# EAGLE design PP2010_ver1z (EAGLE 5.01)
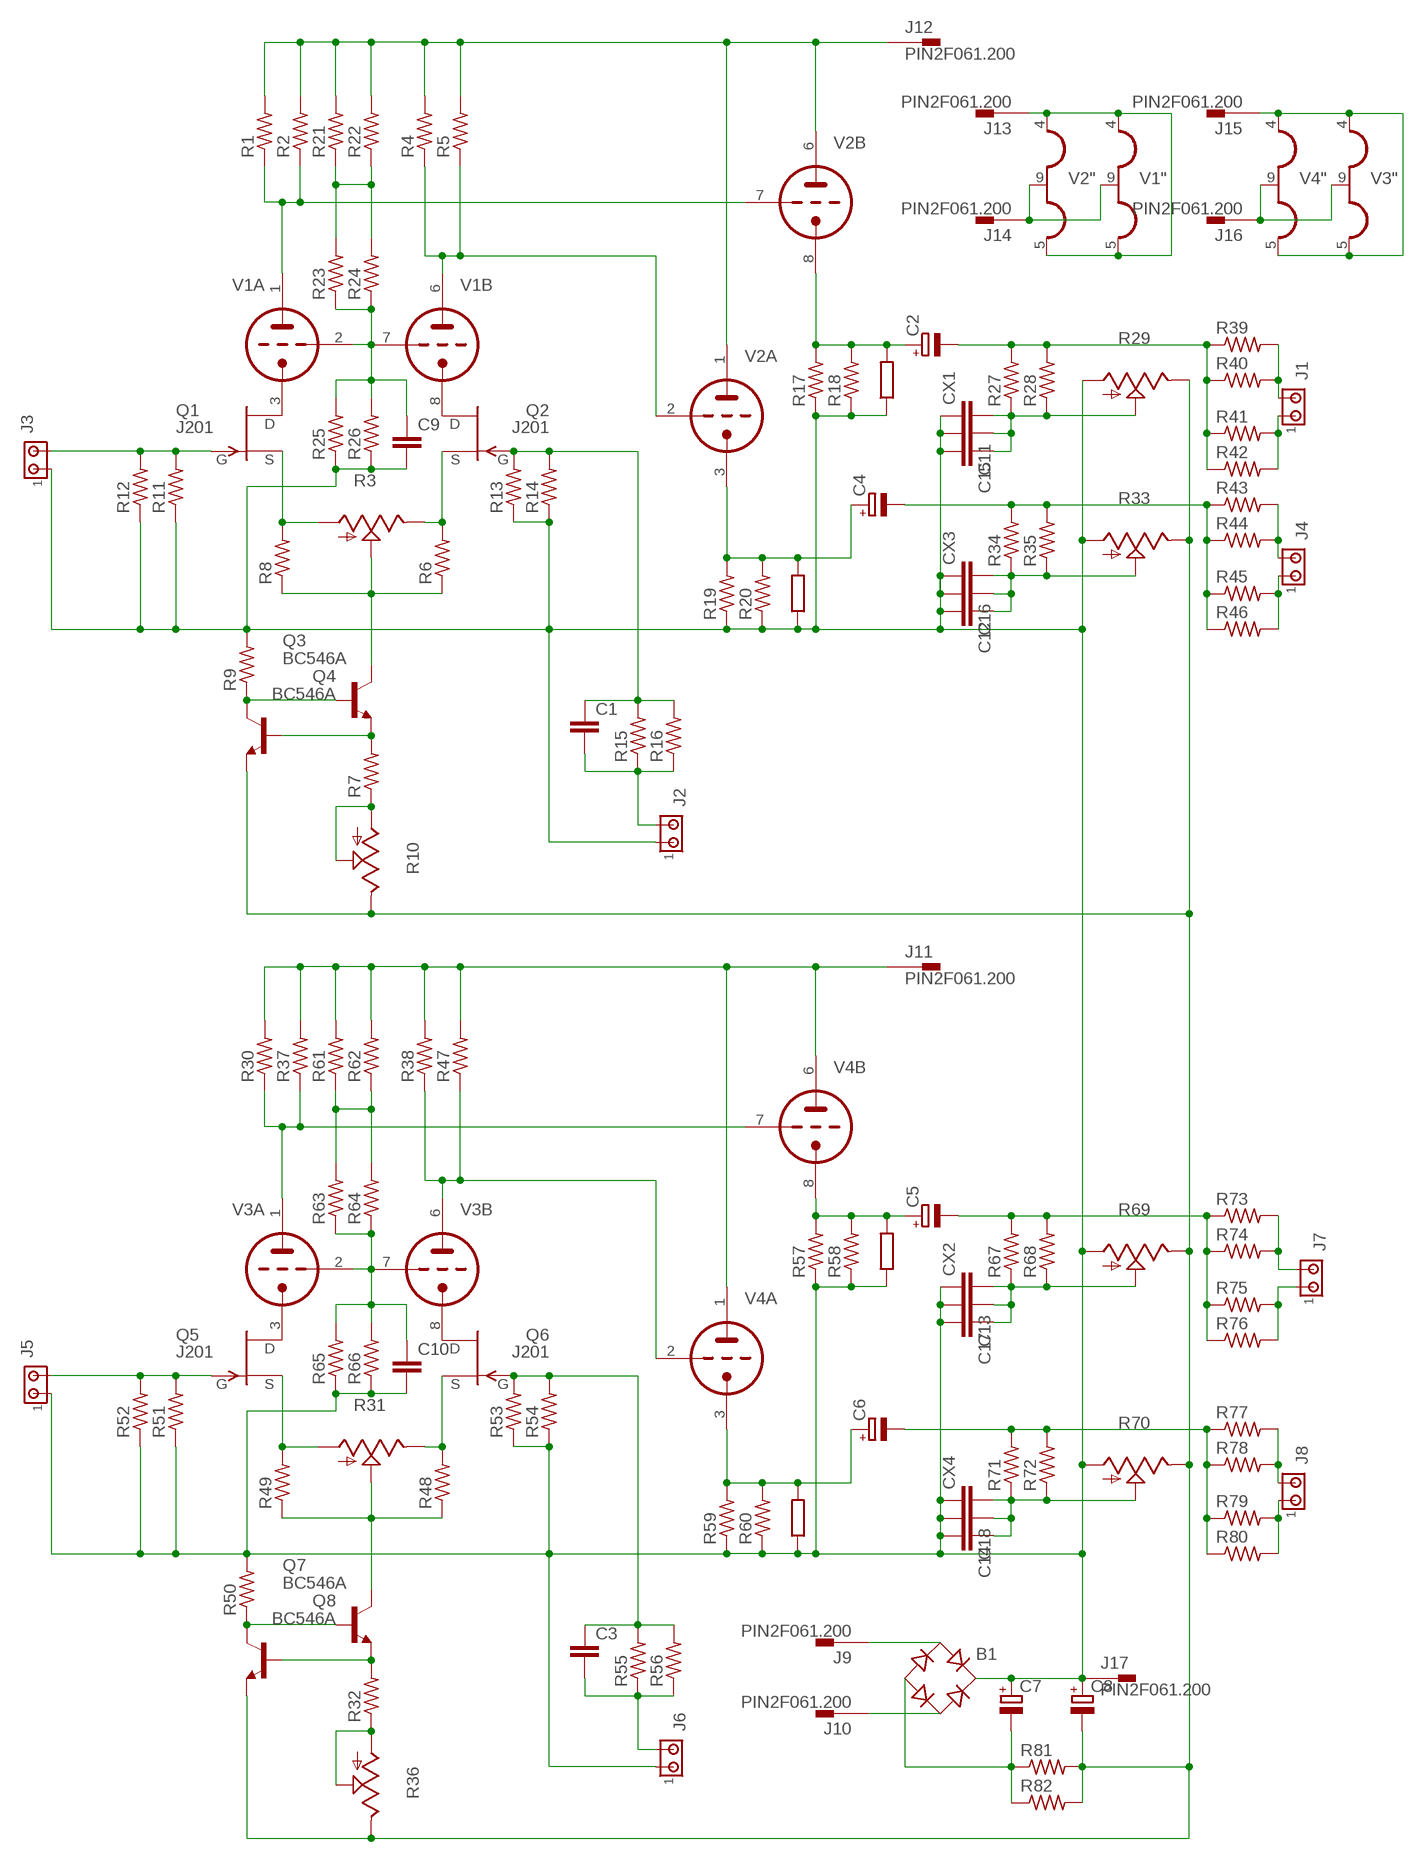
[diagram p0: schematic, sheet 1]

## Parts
B1  RB1A  [RB1A]
C1  C-EU025-050X050  [C025-050X050]
C2  CPOL-EUE55-30AXIAL  [E55-30]
C3  C-EU025-050X050  [C025-050X050]
C4  CPOL-EUE55-30AXIAL  [E55-30]
C5  CPOL-EUE55-30AXIAL  [E55-30]
C6  CPOL-EUE55-30AXIAL  [E55-30]
C7  CPOL-EUE7.5-18  [E7,5-18]
C8  CPOL-EUE7.5-18  [E7,5-18]
C9  C-EU150-091X182  [C150-091X182]
C10  C-EU150-091X182  [C150-091X182]
C11  C-EU275-134X316  [C275-134X316]
C12  C-EU275-134X316  [C275-134X316]
C13  C-EU275-134X316  [C275-134X316]
C14  C-EU275-134X316  [C275-134X316]
C15  C-EU150-084X183  [C150-084X183]
C16  C-EU150-084X183  [C150-084X183]
C17  C-EU150-084X183  [C150-084X183]
C18  C-EU150-084X183  [C150-084X183]
CX1  CXXC22B7  [XC22B7]
CX2  CXXC22B7  [XC22B7]
CX3  CXXC22B7  [XC22B7]
CX4  CXXC22B7  [XC22B7]
J1  MTA02-100  [10X02MTA]
J2  MTA02-100  [10X02MTA]
J3  MTA02-100  [10X02MTA]
J4  MTA02-100  [10X02MTA]
J5  MTA02-100  [10X02MTA]
J6  MTA02-100  [10X02MTA]
J7  MTA02-100  [10X02MTA]
J8  MTA02-100  [10X02MTA]
J9  PIN2F061.200  [F061.200]
J10  PIN2F061.200  [F061.200]
J11  PIN2F061.200  [F061.200]
J12  PIN2F061.200  [F061.200]
J13  PIN2F061.200  [F061.200]
J14  PIN2F061.200  [F061.200]
J15  PIN2F061.200  [F061.200]
J16  PIN2F061.200  [F061.200]
J17  PIN2F061.200  [F061.200]
Q1  J201  [TO92]
Q2  J201  [TO92]
Q3  BC546A  [TO92-EBC]
Q4  BC546A  [TO92-EBC]
Q5  J201  [TO92]
Q6  J201  [TO92]
Q7  BC546A  [TO92-EBC]
Q8  BC546A  [TO92-EBC]
R1  R-US_0207/7  [0207/7]
R2  R-US_0207/7  [0207/7]
R3  TRIM_US-B64Y  [B64Y]
R4  R-US_0207/7  [0207/7]
R5  R-US_0207/7  [0207/7]
R6  R-US_0207/7  [0207/7]
R7  R-US_0207/7  [0207/7]
R8  R-US_0207/7  [0207/7]
R9  R-US_0207/7  [0207/7]
R10  TRIM_US-B64Y  [B64Y]
R11  R-US_0207/7  [0207/7]
R12  R-US_0207/7  [0207/7]
R13  R-US_0207/7  [0207/7]
R14  R-US_0207/7  [0207/7]
R15  R-US_0207/7  [0207/7]
R16  R-US_0207/7  [0207/7]
R17  R-US_0617/22  [0617/22]
R18  R-US_0617/22  [0617/22]
R19  R-US_0617/22  [0617/22]
R20  R-US_0617/22  [0617/22]
R21  R-US_0207/7  [0207/7]
R22  R-US_0207/7  [0207/7]
R23  R-US_0207/7  [0207/7]
R24  R-US_0207/7  [0207/7]
R25  R-US_0207/7  [0207/7]
R26  R-US_0207/7  [0207/7]
R27  R-US_0309/10  [0309/10]
R28  R-US_0309/10  [0309/10]
R29  TRIM_US-B64Y  [B64Y]
R30  R-US_0207/7  [0207/7]
R31  TRIM_US-B64Y  [B64Y]
R32  R-US_0207/7  [0207/7]
R33  TRIM_US-B64Y  [B64Y]
R34  R-US_0309/10  [0309/10]
R35  R-US_0309/10  [0309/10]
R36  TRIM_US-B64Y  [B64Y]
R37  R-US_0207/7  [0207/7]
R38  R-US_0207/7  [0207/7]
R39  R-US_0309/10  [0309/10]
R40  R-US_0309/10  [0309/10]
R41  R-US_0309/10  [0309/10]
R42  R-US_0309/10  [0309/10]
R43  R-US_0309/10  [0309/10]
R44  R-US_0309/10  [0309/10]
R45  R-US_0309/10  [0309/10]
R46  R-US_0309/10  [0309/10]
R47  R-US_0207/7  [0207/7]
R48  R-US_0207/7  [0207/7]
R49  R-US_0207/7  [0207/7]
R50  R-US_0207/7  [0207/7]
R51  R-US_0207/7  [0207/7]
R52  R-US_0207/7  [0207/7]
R53  R-US_0207/7  [0207/7]
R54  R-US_0207/7  [0207/7]
R55  R-US_0207/7  [0207/7]
R56  R-US_0207/7  [0207/7]
R57  R-US_0617/22  [0617/22]
R58  R-US_0617/22  [0617/22]
R59  R-US_0617/22  [0617/22]
R60  R-US_0617/22  [0617/22]
R61  R-US_0207/7  [0207/7]
R62  R-US_0207/7  [0207/7]
R63  R-US_0207/7  [0207/7]
R64  R-US_0207/7  [0207/7]
R65  R-US_0207/7  [0207/7]
R66  R-US_0207/7  [0207/7]
R67  R-US_0309/10  [0309/10]
R68  R-US_0309/10  [0309/10]
R69  TRIM_US-B64Y  [B64Y]
R70  TRIM_US-B64Y  [B64Y]
R71  R-US_0309/10  [0309/10]
R72  R-US_0309/10  [0309/10]
R73  R-US_0309/10  [0309/10]
R74  R-US_0309/10  [0309/10]
R75  R-US_0309/10  [0309/10]
R76  R-US_0309/10  [0309/10]
R77  R-US_0309/10  [0309/10]
R78  R-US_0309/10  [0309/10]
R79  R-US_0309/10  [0309/10]
R80  R-US_0309/10  [0309/10]
R81  R-US_0617/22  [0617/22]
R82  R-US_0617/22  [0617/22]
U$1  MP820  [MP820]
U$2  MP820  [MP820]
U$3  MP820  [MP820]
U$4  MP820  [MP820]
V1  12AX7-P  [NOVAL]
V2  12AU7-P  [NOVAL]
V3  12AX7-P  [NOVAL]
V4  12AU7-P  [NOVAL]

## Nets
N$1: C4.- R34.2 R35.2 R43.1 R44.1 R45.1 R46.1
N$2: R1.1 R2.1 V1.1(A:TA) V2.7(B:TG)
N$3: Q3.E Q4.B R7.2
N$4: R4.1 R5.1 V1.6(B:TA) V2.2(A:TG)
N$5: J12.1A R1.2 R2.2 R4.2 R5.2 R21.2 R22.2 V2.1(A:TA) V2.6(B:TA)
N$6: Q1.3(D) V1.3(A:TK)
N$7: Q2.3(D) V1.8(B:TK)
N$8: Q1.2(S) R3.A R8.2
N$9: C2.+ R17.2 R18.2 U$4.OUT V2.8(B:TK)
N$10: Q2.2(S) R3.E R6.2
N$11: R7.1 R10.A R10.S
N$12: Q3.C R3.S R6.1 R8.1
N$13: Q3.B Q4.C R9.1
N$14: C8.- Q4.E Q8.E R10.E R29.E R33.E R36.E R69.E R70.E R81.2 R82.2
N$15: J3.2 Q1.1(G) R11.2 R12.2
N$16: R21.1 R22.1 R23.2 R24.2
N$17: B1.AC1 J9.1A
N$18: C4.+ R19.2 R20.2 U$3.OUT V2.3(A:TK)
N$19: C1.1 Q2.1(G) R13.2 R14.2 R15.2 R16.2
N$20: C1.2 J2.2 R15.1 R16.1
N$21: C9.1 R23.1 R24.1 R25.2 R26.2 V1.2(A:TG) V1.7(B:TG)
N$22: C2.- R27.2 R28.2 R39.1 R40.1 R41.1 R42.1
N$23: C11.1 C15.1 CX1.2 R27.1 R28.1 R29.S
N$24: J1.2 R39.2 R40.2
N$25: J1.1 R41.2 R42.2
N$26: J4.2 R43.2 R44.2
N$27: J4.1 R45.2 R46.2
N$28: B1.AC2 J10.1A
N$29: Q6.2(S) R31.E R48.2
N$30: C12.1 C16.1 CX3.2 R33.S R34.1 R35.1
N$31: R30.1 R37.1 V3.1(A:TA) V4.7(B:TG)
N$32: R38.1 R47.1 V3.6(B:TA) V4.2(A:TG)
N$33: J11.1A R30.2 R37.2 R38.2 R47.2 R61.2 R62.2 V4.1(A:TA) V4.6(B:TA)
N$34: Q5.3(D) V3.3(A:TK)
N$35: Q6.3(D) V3.8(B:TK)
N$36: Q5.2(S) R31.A R49.2
N$37: Q7.C R31.S R48.1 R49.1
N$38: Q7.E Q8.B R32.2
N$39: R32.1 R36.A R36.S
N$40: Q7.B Q8.C R50.1
N$41: J15.1A V3.4(":H1) V3.5(":H3) V4.4(":H1) V4.5(":H3)
N$42: J5.2 Q5.1(G) R51.2 R52.2
N$43: C3.1 Q6.1(G) R53.2 R54.2 R55.2 R56.2
N$44: C3.2 J6.2 R55.1 R56.1
N$45: C5.+ R57.2 R58.2 U$2.OUT V4.8(B:TK)
N$46: J16.1A V3.9(":H2) V4.9(":H2)
N$47: C6.+ R59.2 R60.2 U$1.OUT V4.3(A:TK)
N$48: C5.- R67.2 R68.2 R73.1 R74.1 R75.1 R76.1
N$49: C6.- R71.2 R72.2 R77.1 R78.1 R79.1 R80.1
N$50: R61.1 R62.1 R63.2 R64.2
N$51: C10.1 R63.1 R64.1 R65.2 R66.2 V3.2(A:TG) V3.7(B:TG)
N$52: C13.1 C17.1 CX2.2 R67.1 R68.1 R69.S
N$53: C14.1 C18.1 CX4.2 R70.S R71.1 R72.1
N$54: J7.2 R73.2 R74.2
N$55: J7.1 R75.2 R76.2
N$56: J8.2 R77.2 R78.2
N$57: J8.1 R79.2 R80.2
N$58: B1.- C7.- R81.1 R82.1
N$59: B1.+ C7.+ C8.+ C9.2 C10.2 C11.2 C12.2 C13.2 C14.2 C15.2 C16.2 C17.2 C18.2 CX1.1 CX2.1 CX3.1 CX4.1 J2.1 J3.1 J5.1 J6.1 J17.1A R9.2 R11.1 R12.1 R13.1 R14.1 R17.1 R18.1 R19.1 R20.1 R25.1 R26.1 R29.A R33.A R50.2 R51.1 R52.1 R53.1 R54.1 R57.1 R58.1 R59.1 R60.1 R65.1 R66.1 R69.A R70.A U$1.IN U$2.IN U$3.IN U$4.IN
N$60: J13.1A V1.4(":H1) V1.5(":H3) V2.4(":H1) V2.5(":H3)
N$61: J14.1A V1.9(":H2) V2.9(":H2)
Unconnected: J9.1B(1.1) J10.1B(1.1) J11.1B(1.1) J12.1B(1.1) J13.1B(1.1) J14.1B(1.1) J15.1B(1.1) J16.1B(1.1) J17.1B(1.1)

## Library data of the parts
B1 = rectifier:RB1A: RECTIFIER 1 A
C1 C3 C9-C18 = rcl:C-EU: CAPACITOR, European symbol
C2 C4-C6 = resistor:CPOL-EU: POLARIZED CAPACITOR, European symbol
C7 C8 = rcl:CPOL-EU: POLARIZED CAPACITOR, European symbol
CX1-CX4 = resistor:CX: X CAPACITOR
J1-J8 = con-amp:MTA02-100: AMP connector
J9-J17 = con-faston:PIN2: Flachstecker Typ Tyco/Electronics/AMP TAB, FASTON
Q1 Q2 Q5 Q6 = transistor-fet:?20*: TEMIC / Siliconix N-Channel JFET Source: JFET-J201_Siliconix_data.pdf
Q3 Q4 Q7 Q8 = transistor-npn:BC546*: NPN Transistor
R1 R2 R4-R9 R11-R16 R21-R26 R30 R32 R37 R38 R47-R56 R61-R66 R81 R82 = rcl:R-US_: RESISTOR, American symbol
R3 R10 R29 R31 R33 R36 R69 R70 = pot:TRIM_US-: POTENTIOMETER
R17-R20 R27 R28 R34 R35 R39-R46 R57-R60 R67 R68 R71-R80 = resistor:R-US_: RESISTOR, American symbol
U$1-U$4 = ciuffoli:MP820
V1 V3 = tubes:12AX7-P
V2 V4 = tubes:12AU7-P

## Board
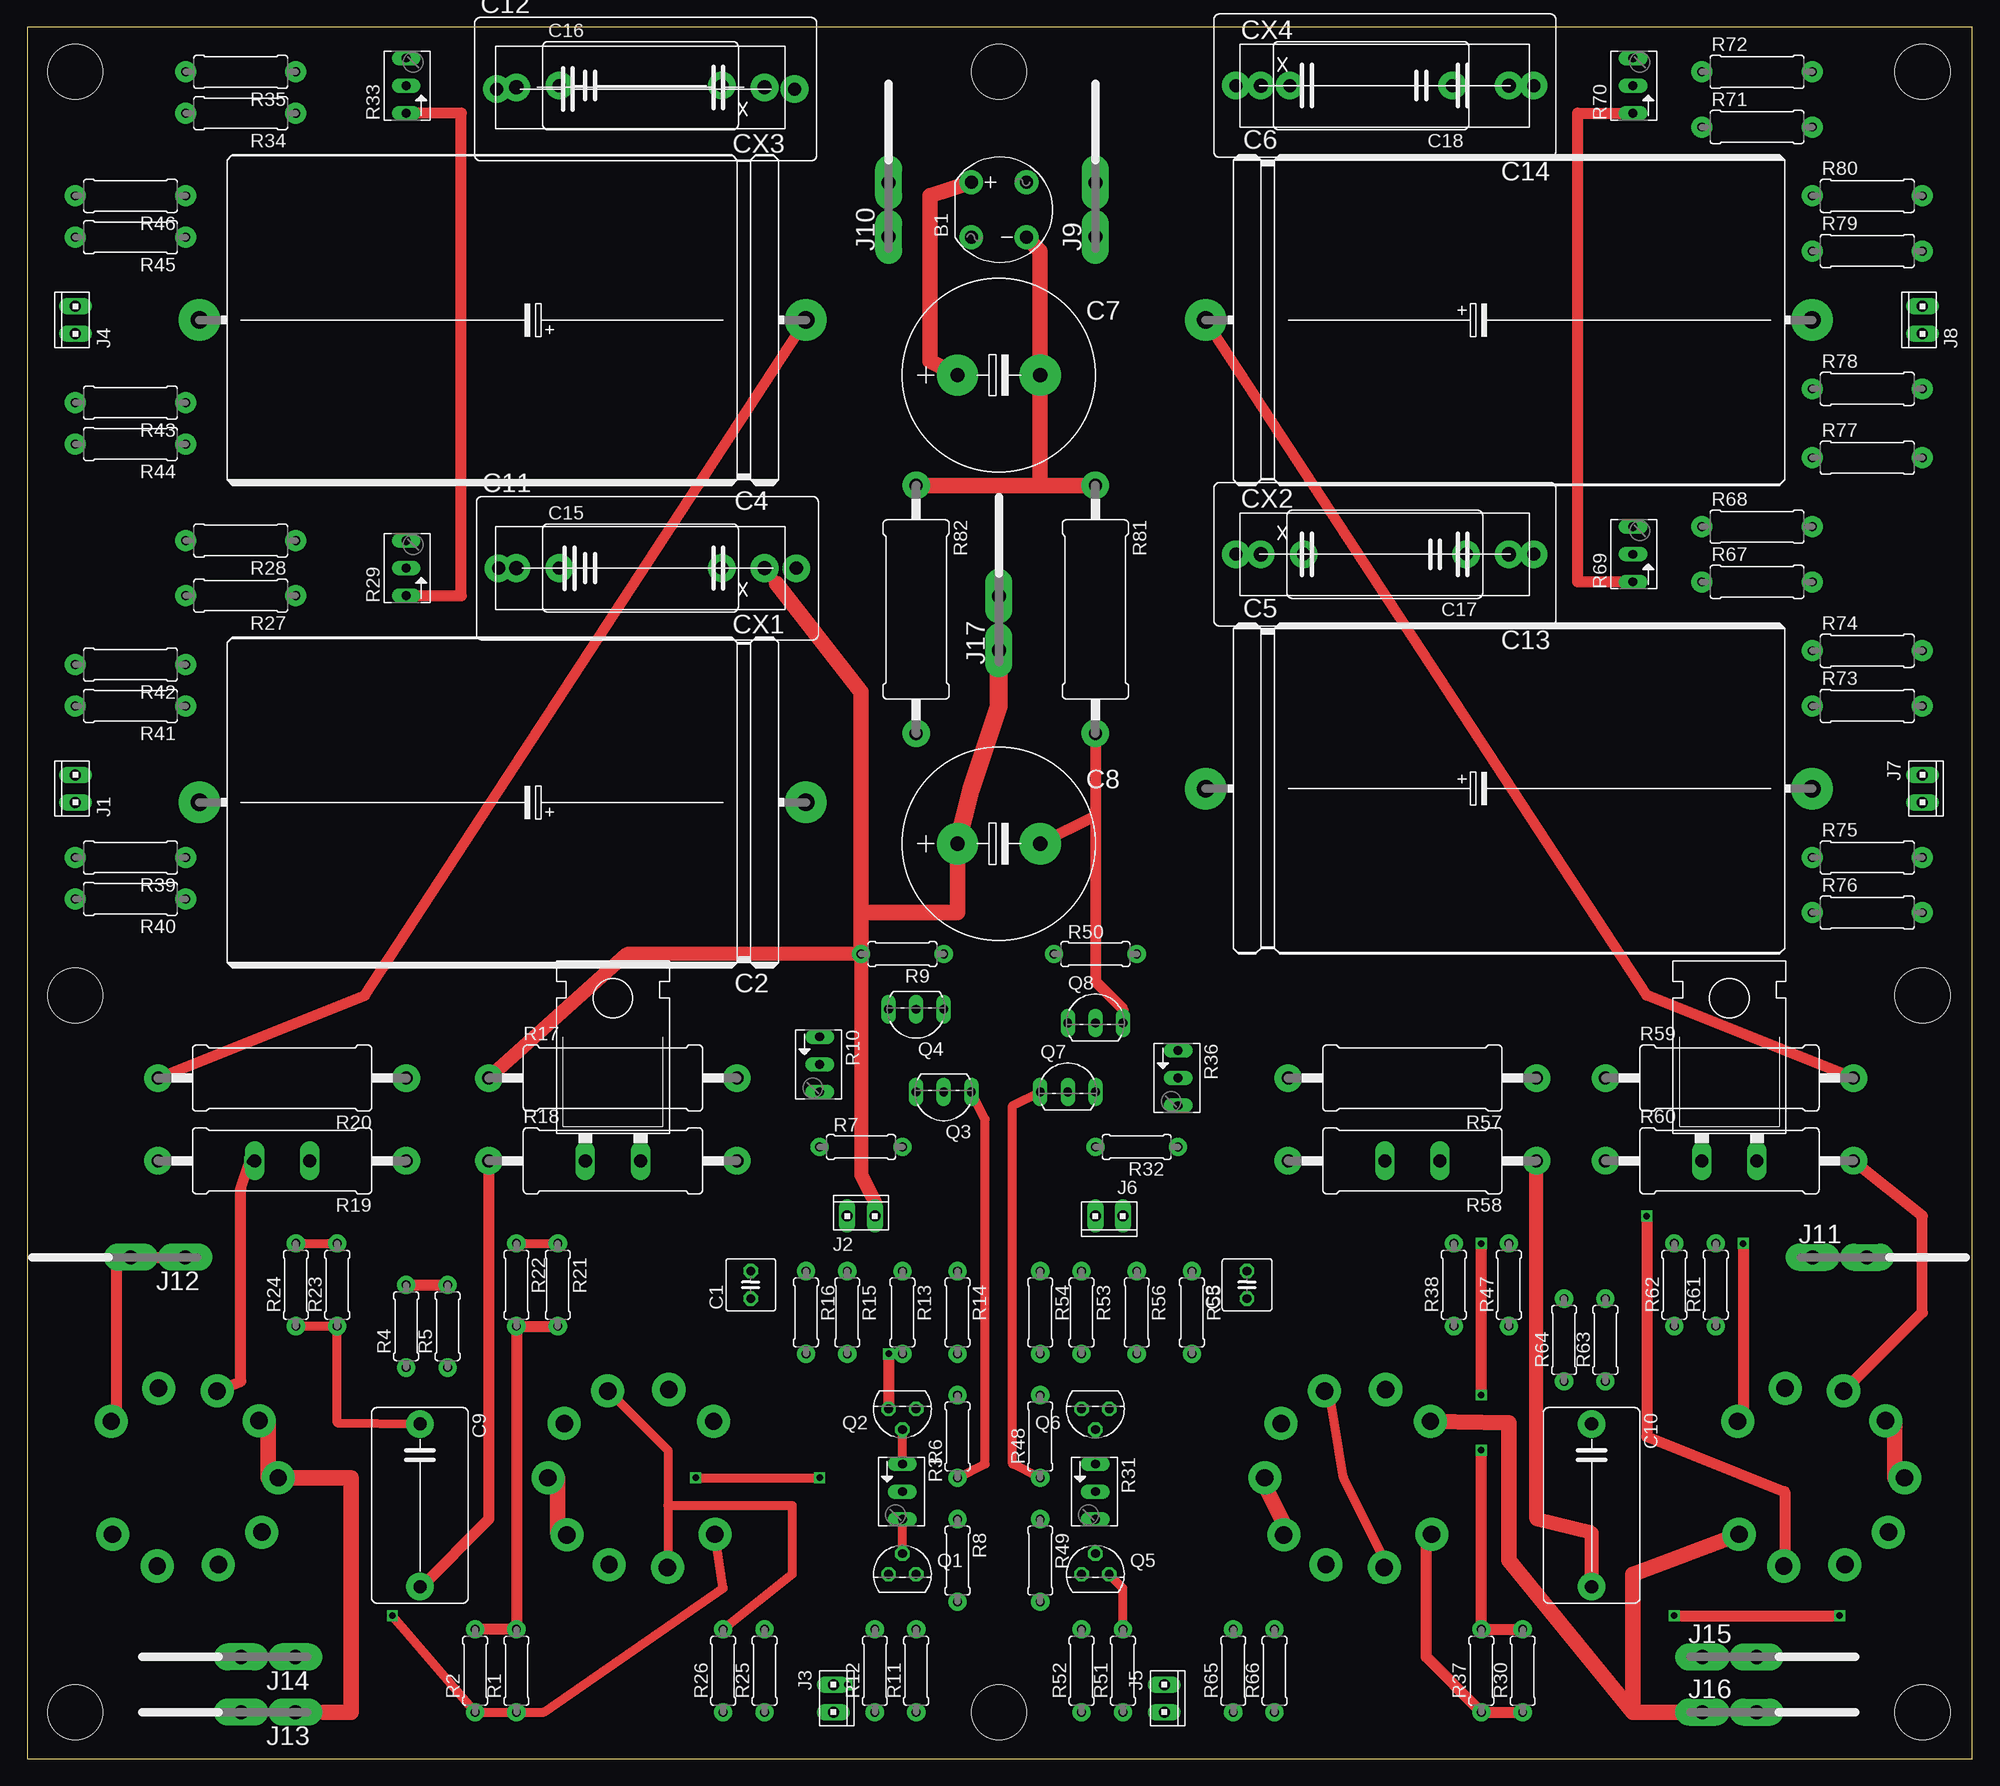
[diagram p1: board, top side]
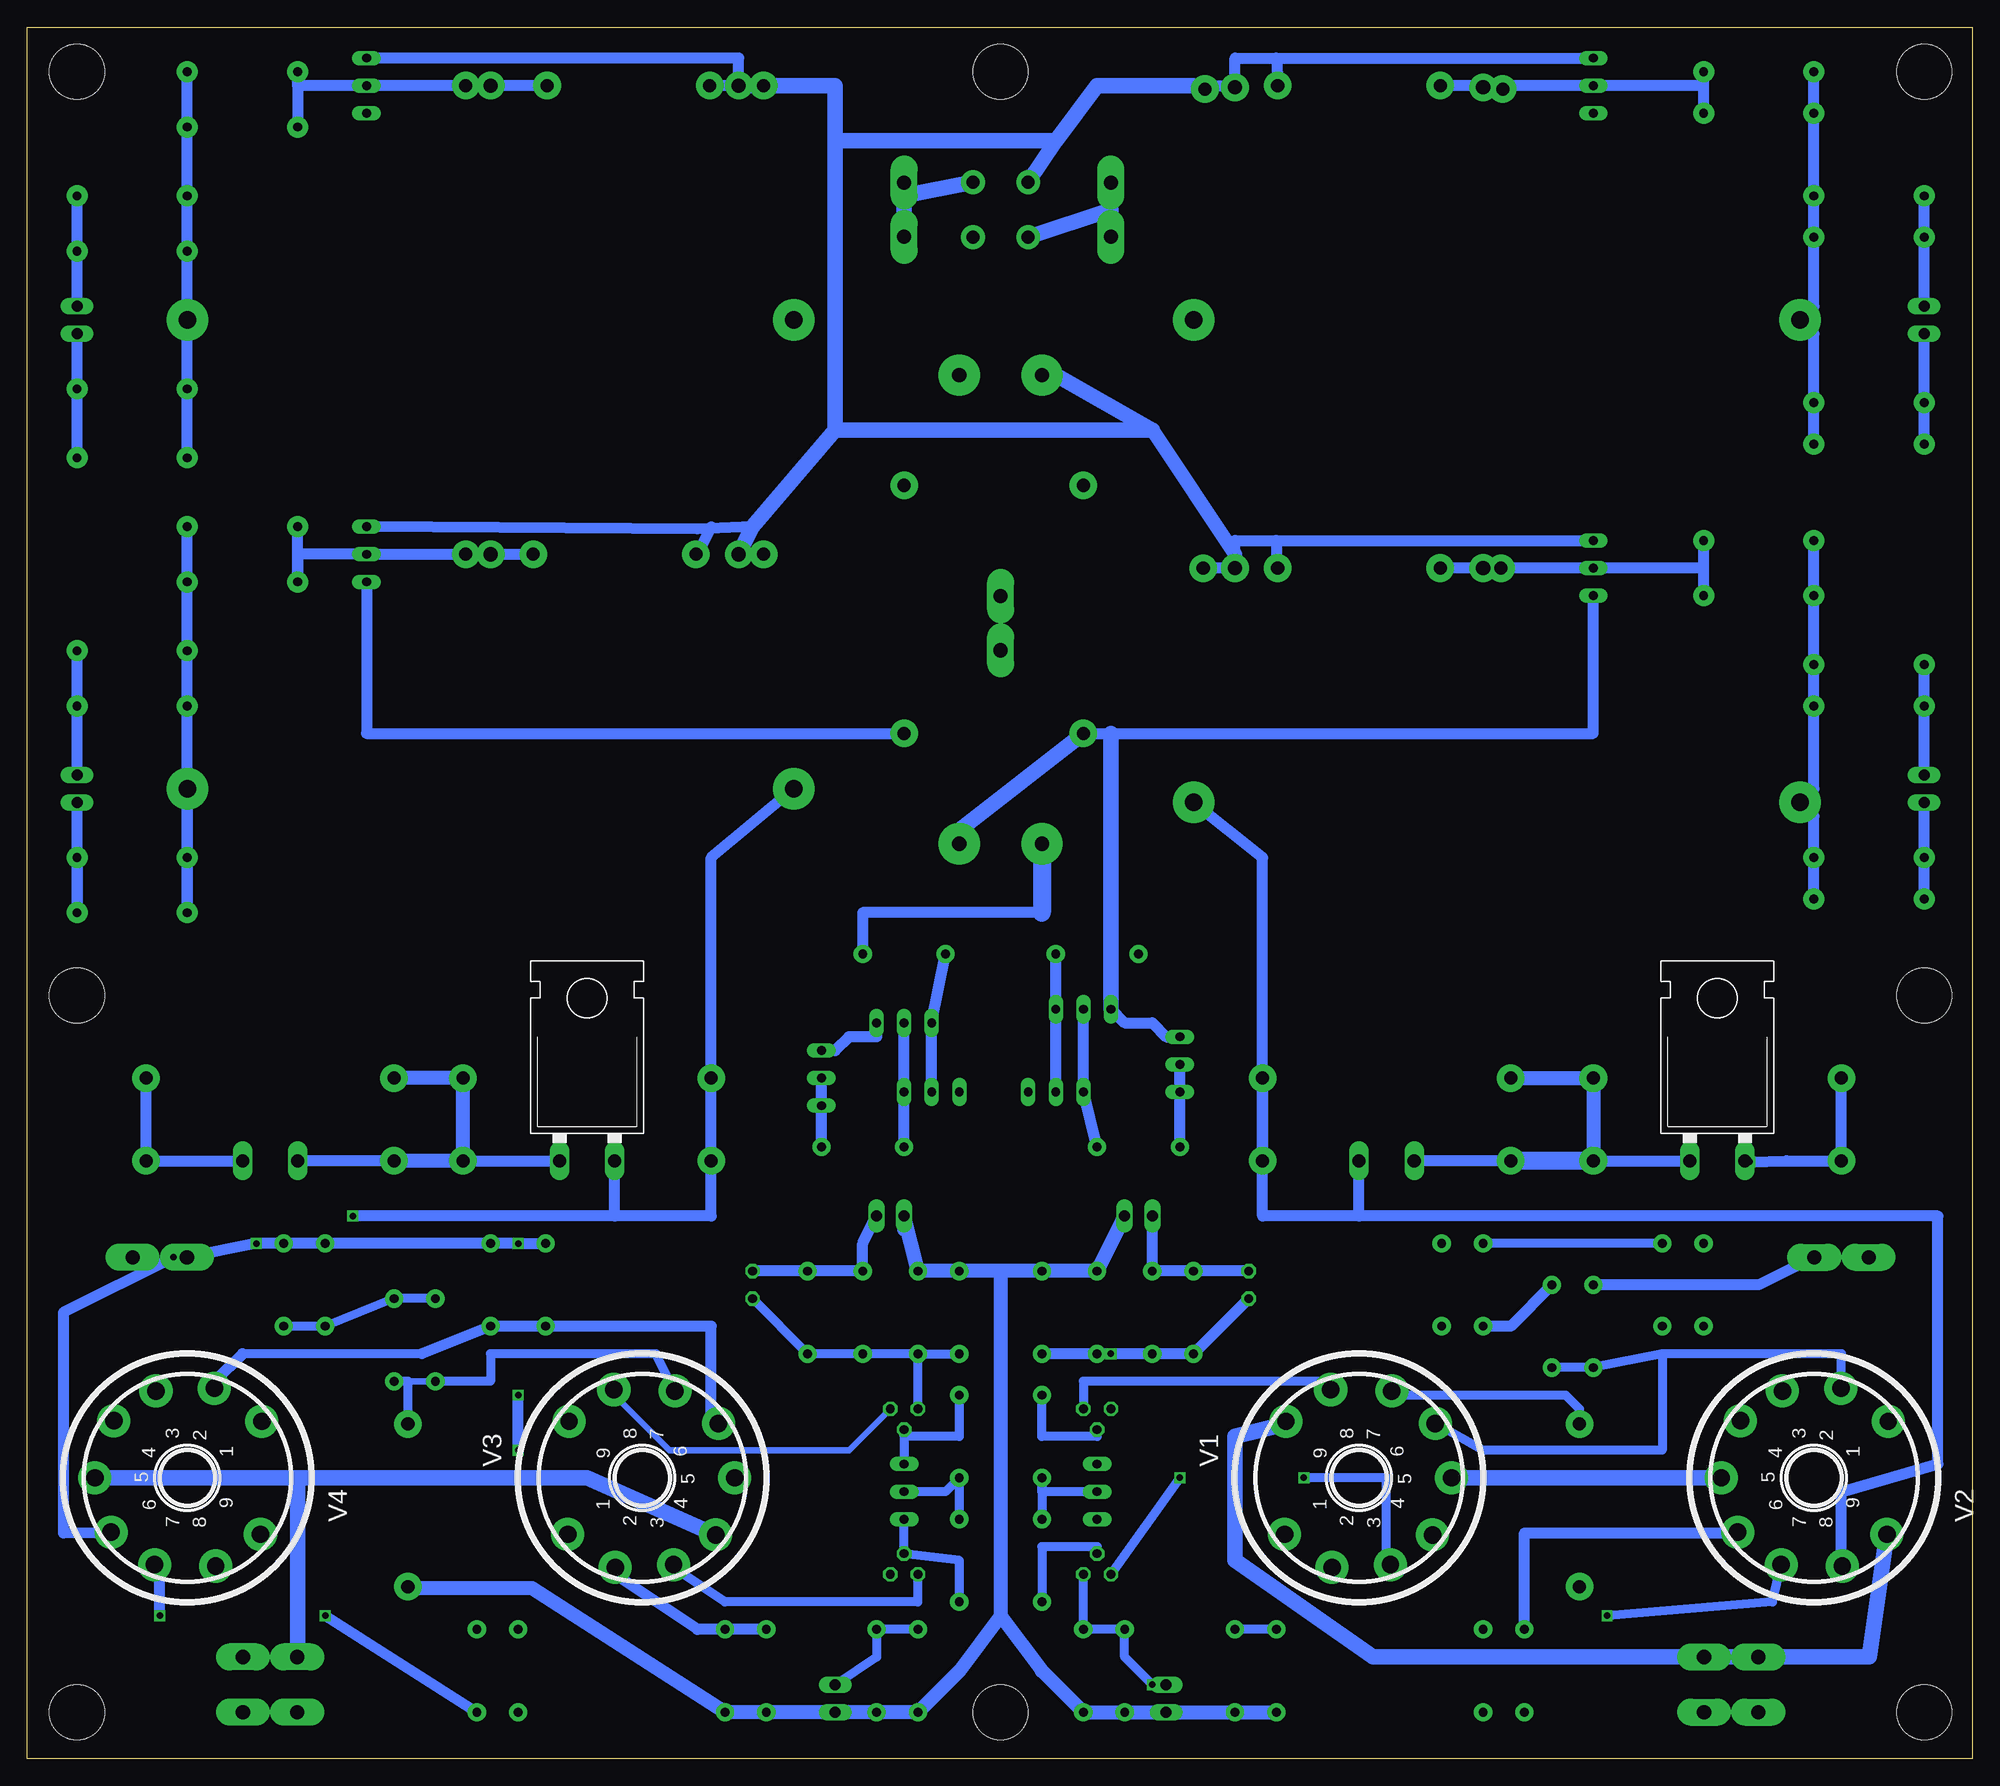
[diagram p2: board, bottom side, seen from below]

Size 179.22 x 159.53 mm. Coordinates in mm from the lower left corner, seen from the top.
Outline: 0,0 179.22,0 179.22,159.53 0,159.53 0,0
Copper layers (1*16): Top 0.035mm / dielectric 1.5mm / Bottom 0.035mm
Design rules "default": minimum track width 10mil, minimum drill 24mil, track to track 8mil, track to pad 8mil, pad to pad 8mil, via to via 8mil, smd to smd 8mil, copper to edge 40mil, drill to drill 8mil, minimum pad ring 10mil, minimum via ring 8mil, stop-mask expansion 4mil, vias tented up to drill 0mil, thermal gap 10mil
Holes 5.08 mm at 89.53,155.41 4.44,155.41 174.62,155.41 4.44,4.28 89.53,4.28 174.62,4.28 4.44,70.32 174.62,70.32

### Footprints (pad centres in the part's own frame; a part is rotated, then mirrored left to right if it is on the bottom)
RB1A = drill 1.2 pad 2.184 round: + -2.54,2.54; - 2.54,-2.54; AC1 2.54,2.54; AC2 -2.54,-2.54
C025-050X050 = drill 0.813 octagon: 1 -1.27,0; 2 1.27,0
E55-30 = drill 1.6 pad 3.81 round: + -27.94,0; - 27.94,0
E7,5-18 = drill 1.3 pad 3.81 round: + -3.81,0; - 3.81,0
C150-091X182 = drill 1.2 pad 2.54 round: 1 -7.493,0; 2 7.493,0
C275-134X316 = drill 1.2 pad 2.54 round: 1 -13.716,0; 2 13.716,0
C150-084X183 = drill 1.2 pad 2.54 round: 1 -7.493,0; 2 7.493,0
XC22B7 = drill 1.3 pad 2.54 round: 1 -11.43,0; 2 11.43,0
10X02MTA = drill 1.016 long: 1 1.27,0; 2 -1.27,0
F061.200 = drill 1.3 pad 2.5 long: 1A -2.5,0; 1B 2.5,0
TO92 = drill 0.813 octagon: 1 1.27,0; 2 0,1.905; 3 -1.27,0
TO92-EBC = drill 0.813 long: B 0,-1.27; C -2.54,-1.27; E 2.54,-1.27
0207/7 = drill 0.813 pad 1.676 round: 1 -3.81,0; 2 3.81,0
B64Y = drill 0.813 long: A 2.54,0; E -2.54,0; S 0,0
0617/22 = drill 1.2 pad 2.54 round: 1 -11.43,0; 2 11.43,0
0309/10 = drill 0.813 pad 1.93 round: 1 -5.08,0; 2 5.08,0
MP820 = drill 1.2 long: IN -3.81,-8.89; OUT 1.27,-8.89
NOVAL = drill 1.6 pad 3.048 round: 1 5.207,-6.858; 2 8.254,-2.484; 3 8.004,2.893; 4 5.258,6.77; 5 0,8.524; 6 -5.004,7.024; 7 -8.004,3.02; 8 -8.127,-2.611; 9 -5.207,-6.731

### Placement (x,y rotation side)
B1  89.53,142.71 0 top
C1  66.67,43.65 90 top
C2  43.81,88.1 180 top
C3  112.39,43.65 90 top
C4  43.81,132.55 180 top
C5  136.52,89.37 0 top
C6  136.52,132.55 0 top
C7  89.53,127.47 0 top
C8  89.53,84.29 0 top
C9  36.19,23.33 270 top
C10  144.14,23.33 270 top
C11  57.15,109.68 0 top
C12  56.99,153.82 0 top
C13  125.09,110.96 180 top
C14  125.09,154.14 180 top
C15  56.51,109.69 0 top
C16  56.51,154.14 0 top
C17  125.09,110.96 180 top
C18  123.82,154.14 180 top
CX1  56.51,109.69 180 top
CX2  125.09,110.96 0 top
CX3  56.51,153.98 180 top
CX4  125.09,154.14 0 top
J1  4.44,89.37 90 top
J2  76.83,50 0 top
J3  74.29,5.55 270 top
J4  4.44,132.55 90 top
J5  104.77,5.55 270 top
J6  99.69,50 180 top
J7  174.62,89.37 270 top
J8  174.62,132.55 90 top
J9  98.42,142.71 90 top
J10  79.37,142.71 90 top
J11  167,46.19 0 top
J12  12.06,46.19 180 top
J13  22.22,4.28 180 top
J14  22.22,9.36 180 top
J15  156.84,9.36 0 top
J16  156.84,4.28 0 top
J17  89.53,104.61 90 top
Q1  80.64,16.98 0 top
Q2  80.64,32.22 180 top
Q3  84.45,60.16 180 top
Q4  81.91,67.78 180 top
Q5  98.42,16.98 0 top
Q6  98.42,32.22 180 top
Q7  95.88,62.7 0 top
Q8  98.42,69.05 0 top
R1  45.08,8.09 90 top
R2  41.27,8.09 90 top
R3  80.64,24.6 270 top
R4  34.92,39.84 90 top
R5  38.73,39.84 90 top
R6  85.72,29.68 90 top
R7  76.83,56.35 0 top
R8  85.72,18.25 270 top
R9  80.64,74.13 180 top
R10  73.02,63.97 270 top
R11  81.91,8.09 90 top
R12  78.1,8.09 90 top
R13  80.64,41.11 270 top
R14  85.72,41.11 270 top
R15  75.56,41.11 270 top
R16  71.75,41.11 270 top
R17  53.97,62.7 0 top
R18  53.97,55.08 0 top
R19  23.49,55.08 180 top
R20  23.49,62.7 180 top
R21  48.89,43.65 270 top
R22  45.08,43.65 270 top
R23  28.57,43.65 90 top
R24  24.76,43.65 90 top
R25  67.94,8.09 90 top
R26  64.13,8.09 90 top
R27  19.68,107.15 180 top
R28  19.68,112.23 180 top
R29  34.92,109.69 90 top
R30  137.79,8.09 90 top
R31  98.42,24.6 270 top
R32  102.23,56.35 180 top
R33  34.92,154.14 90 top
R34  19.68,151.6 180 top
R35  19.68,155.41 180 top
R36  106.04,62.7 270 top
R37  133.98,8.09 90 top
R38  131.44,43.65 90 top
R39  9.52,83.02 180 top
R40  9.52,79.21 180 top
R41  9.52,96.99 180 top
R42  9.52,100.8 180 top
R43  9.52,124.93 180 top
R44  9.52,121.12 180 top
R45  9.52,140.17 180 top
R46  9.52,143.98 180 top
R47  136.52,43.65 90 top
R48  93.34,29.68 90 top
R49  93.34,18.25 270 top
R50  98.42,74.13 0 top
R51  100.96,8.09 90 top
R52  97.15,8.09 90 top
R53  97.15,41.11 270 top
R54  93.34,41.11 270 top
R55  107.31,41.11 270 top
R56  102.23,41.11 270 top
R57  127.63,62.7 180 top
R58  127.63,55.08 180 top
R59  156.84,62.7 0 top
R60  156.84,55.08 0 top
R61  155.57,43.65 90 top
R62  151.76,43.65 90 top
R63  145.41,38.57 90 top
R64  141.6,38.57 90 top
R65  111.12,8.09 90 top
R66  114.93,8.09 90 top
R67  159.38,108.42 0 top
R68  159.38,113.5 0 top
R69  147.95,110.96 90 top
R70  147.95,154.14 90 top
R71  159.38,150.33 0 top
R72  159.38,155.41 0 top
R73  169.54,96.99 0 top
R74  169.54,102.07 0 top
R75  169.54,83.02 0 top
R76  169.54,77.94 0 top
R77  169.54,119.85 0 top
R78  169.54,126.2 0 top
R79  169.54,138.9 0 top
R80  169.54,143.98 0 top
R81  98.42,105.88 270 top
R82  81.91,105.88 270 top
U$1  158.11,63.97 0 top
U$2  126.36,63.97 0 bottom
U$3  22.22,63.97 0 bottom
U$4  55.24,63.97 0 top
V1  56.51,25.87 270 bottom
V2  14.6,25.87 90 bottom
V3  122.55,25.87 270 bottom
V4  164.46,25.87 90 bottom

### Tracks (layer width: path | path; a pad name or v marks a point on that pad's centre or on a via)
N$1
  Bottom 1.016: R35.2 R34.2 R46.1 R45.1 14.6,133.82 C4.- 14.6,131.28 R43.1 R44.1
N$2  (via drill 0.6)
  Top 0.813: v33.65,13.17 R2.1 R1.1 47.62,4.28 64.13,15.71 V1.1
  Bottom 0.813: v33.65,13.17 18.41,14.44 V2.7
N$3
  Bottom 1.016: Q4.B Q3.E R7.2
N$4
  Bottom 0.254: V2.2 12.06,34.76
  Bottom 0.813: R5.1 R4.1 28.57,37.3 | 28.57,37.3 12.06,37.3 12.06,34.76 | 28.57,37.3 28.57,28.41 45.08,28.41 V1.6
N$5
  Top 1.016: J12.1A 8.25,46.19 8.25,32.22 V2.1 | R4.2 R5.2 | R21.2 R22.2 R1.2 R2.2
  Bottom 0.254: 22.22,20.79 V2.6 | J12.1A 14.6,46.19
  Bottom 1.016: R5.2 42.54,39.84 R22.2 | R2.2 41.27,20.79 22.22,20.79 | 14.6,46.19 19.68,43.65 R4.2
N$6  (via drill 0.6)
  Top 0.813: v61.59,25.87 v73.02,25.87
  Bottom 0.813: v73.02,25.87 Q1.3 | v61.59,25.87 53.97,25.87 53.97,18.25 V1.3
N$7
  Bottom 0.813: Q2.3 81.91,34.76 59.05,34.76 V1.8
N$8
  Top 0.813: Q1.2 R3.A
  Bottom 0.813: R8.2 85.72,19.52 80.64,19.52 Q1.2
N$9
  Bottom 0.254: V2.8 12.06,17.74
  Bottom 1.016: 56.51,50 3.17,50 3.17,27.14 12.06,24.6 12.06,17.74 | 56.51,50 65.4,50 | 65.4,50 R17.2 R18.2 | 65.4,50 65.4,83.02 C2.+ | 56.51,50 U$4.OUT
N$10
  Top 0.813: R3.E Q2.2
  Bottom 0.813: R6.2 85.72,29.68 80.64,29.68 Q2.2
N$11
  Bottom 1.016: R10.S R10.A R7.1
N$12
  Top 0.813: Q3.C 88.26,58.89 88.26,27.14 R6.1
  Bottom 0.254: R3.S 81.91,24.6
  Bottom 0.813: 81.91,24.6 85.72,24.6 R6.1 R8.1
N$13
  Bottom 1.016: Q3.B Q4.C R9.1
N$14
  Top 1.016: R29.E 40,107.15 40,151.6 R33.E | R69.E 142.87,108.42 142.87,151.6 R70.E | R81.2 98.42,86.83 | 98.42,86.83 98.42,71.59 100.96,69.05 Q8.E | 98.42,86.83 C8.-
  Bottom 1.016: R10.E 74.29,66.51 75.56,67.78 78.1,67.78 Q4.E | R29.E 34.92,94.45 79.37,94.45 R82.2 | R36.E 104.77,65.24 103.5,66.51 100.96,66.51 Q8.E | R69.E 147.95,94.45 R81.2 | C8.- 93.34,85.56
  Bottom 1.422: 79.37,94.45 Q4.E | 93.34,85.56 R82.2
N$15  (via drill 0.6)
  Top 0.254: J3.2 v75.56,6.82
  Bottom 0.813: Q1.1 R11.2 R12.2 78.1,9.36 v75.56,6.82
N$16
  Top 0.813: R24.2 R23.2 | R22.1 R21.1
  Bottom 0.813: R23.2 R22.1
N$17
  Bottom 1.422: B1.AC1 98.42,143.98 J9.1A 98.42,138.9
N$18  (via drill 0.6)
  Top 1.016: v20.52,54.99 19.68,52.54 19.68,34.76 V2.3 | R20.2 31.11,70.32 C4.+
  Bottom 1.016: R20.2 R19.2 17.14,55.08 v20.52,54.99
N$19  (via drill 0.6)
  Top 1.016: v79.37,37.3 Q2.1
  Bottom 1.016: R14.2 R13.2 v79.37,37.3 R15.2 R16.2 C1.1
N$20
  Bottom 1.016: C1.2 R16.1 R15.1 J2.2
N$21
  Top 0.254: 59.05,16.98 V1.2 | V1.7 53.97,33.49
  Top 0.813: R24.1 R23.1 28.57,30.95 C9.1 | 59.05,23.33 59.05,16.98 | 59.05,23.33 70.48,23.33 70.48,16.98 R26.2 | 53.97,33.49 59.05,28.41 59.05,23.33 | 59.05,23.33 59.05,18.25 V1.2
  Bottom 0.813: R26.2 R25.2 | C9.1 36.19,32.22 37.46,33.49 52.7,33.49 V1.7
N$22
  Bottom 1.016: R28.2 R27.2 R42.1 R41.1 14.6,89.37 C2.- 14.6,86.83 R39.1 R40.1
N$23
  Bottom 0.254: 43.81,109.69 C11.1
  Bottom 1.016: 24.76,109.69 R28.1 | R27.1 24.76,109.69 | 24.76,109.69 R29.S 43.81,109.69 CX1.2 C15.1
N$24
  Bottom 1.016: J1.2 R39.2 R40.2
N$25
  Bottom 1.016: J1.1 R41.2 R42.2
N$26
  Bottom 1.016: J4.2 R43.2 R44.2
N$27
  Bottom 1.016: J4.1 R45.2 R46.2
N$28
  Bottom 1.422: B1.AC2 79.37,142.71 J10.1A
N$29
  Bottom 0.813: R31.E Q6.2 98.42,29.68 93.34,29.68 R48.2
N$30
  Bottom 0.254: 43.81,154.14 C12.1
  Bottom 1.016: 24.76,154.14 R35.1 | R34.1 24.76,154.14 | 45.08,154.14 43.81,154.14 R33.S 24.76,154.14 | 45.08,154.14 CX3.2 | 45.08,154.14 C16.1
N$31  (via drill 0.6)
  Top 1.016: R30.1 R37.1 128.9,9.36 128.9,19.52 V3.1 | v151.76,13.17 v167,13.17
  Bottom 1.016: v167,13.17 167,16.98 V4.7 | R30.1 v151.76,13.17
N$32
  Bottom 0.254: 161.92,34.76 V4.2
  Bottom 0.61: V3.6 116.2,30.95
  Bottom 0.813: 142.87,37.3 159.38,37.3
  Bottom 1.016: 142.87,37.3 R47.1 R38.1 116.2,39.84 116.2,30.95 | 159.38,37.3 161.92,34.76
N$33  (via drill 0.6)
  Top 0.254: J11.1A v165.73,46.19
  Top 0.813: 158.11,32.22 V4.1
  Top 1.016: R30.2 R37.2 v133.98,28.41 | v133.98,33.49 v133.98,47.46 | v158.11,47.46 158.11,32.22
  Bottom 0.813: R61.2 v158.11,47.46
  Bottom 1.016: v133.98,28.41 v133.98,33.49 | R38.2 v133.98,47.46 R47.2 R62.2 R61.2 v158.11,47.46 J11.1A | v165.73,46.19 175.89,41.11 175.89,20.79 V4.6
N$34
  Bottom 0.813: Q5.3 97.15,14.44 114.93,14.44 118.74,16.98 V3.3
N$35
  Bottom 0.254: 125.09,33.49 V3.8
  Bottom 0.61: Q6.3 103.5,28.41 120.01,28.41 125.09,33.49
N$36
  Bottom 0.813: R31.A Q5.2 93.34,18.25 R49.2
N$37
  Top 0.813: Q7.C 90.8,60.16 90.8,27.14 R48.1
  Bottom 0.254: 97.15,24.6 R31.S
  Bottom 0.813: 97.15,24.6 94.61,24.6 R48.1 R49.1
N$38
  Bottom 1.016: Q8.B Q7.E R32.2
N$39
  Bottom 1.016: R36.S R36.A R32.1
N$40
  Bottom 1.016: Q7.B Q8.C R50.1
N$41
  Top 0.254: V3.4 116.2,20.79 | V4.5 172.08,25.87
  Top 1.422: 116.2,20.79 113.66,25.87 V3.5 | 172.08,25.87 172.08,30.95 V4.4
  Bottom 0.254: V3.4 116.2,20.79
  Bottom 1.422: 154.3,25.87 154.3,9.36 J15.1A | 154.3,25.87 V4.5 | 116.2,20.79 127.63,25.87 154.3,25.87
N$42
  Top 0.813: Q5.1 100.96,15.71 R51.2
  Bottom 0.813: J5.2 100.96,9.36 R51.2 R52.2
N$43
  Bottom 0.813: C3.1 R55.2 R56.2 R53.2 | Q6.1 R53.2 | R53.2 R54.2
N$44
  Bottom 1.016: C3.2 R55.1 R56.1 102.23,47.46 J6.2
N$45  (via drill 0.6)
  Top 0.254: 161.92,18.25 V4.8
  Top 1.016: 161.92,18.25 161.92,24.6 149.22,29.68 v149.22,50
  Bottom 0.254: R57.2 R58.2
  Bottom 1.016: 116.2,50 125.09,50 | 125.09,50 v149.22,50 | 116.2,50 R57.2 | 116.2,50 116.2,83.02 C5.+ | 125.09,50 U$2.OUT
N$46
  Top 1.422: 147.95,4.28 J16.1A | 147.95,4.28 147.95,16.98 V4.9 | 147.95,4.28 136.52,18.25 136.52,30.95 V3.9
N$47
  Top 1.016: R60.2 174.62,50 174.62,41.11 168.27,34.76 V4.3 | R59.2 149.22,70.32 C6.+
  Bottom 1.016: R59.2 R60.2 U$1.OUT
N$48
  Bottom 1.016: R74.1 R73.1 C5.- R76.1 | R74.1 R67.2 R68.2 | R76.1 R75.1 | R76.1 R74.1
N$49
  Bottom 1.016: R77.1 R78.1 C6.- R79.1 R80.1 R71.2 R72.2
N$50
  Bottom 0.813: R61.1 R62.1 R63.2 R64.2
N$51
  Top 0.254: 120.01,33.49 V3.7 | V3.2 125.09,18.25
  Top 0.813: 120.01,33.49 121.28,25.87 125.09,18.25
  Bottom 0.254: 125.09,16.98 V3.2 | V3.7 120.01,34.76
  Bottom 0.61: R64.1 144.14,34.76
  Bottom 0.813: R63.1 144.14,34.76 C10.1 | R64.1 136.52,34.76 136.52,37.3 121.28,37.3 120.01,34.76
  Bottom 1.016: R65.2 R66.2 117.47,11.9 125.09,16.98
N$52
  Bottom 1.016: R68.1 R67.1 154.3,110.96 R69.S C13.1 CX2.2 C17.1
N$53
  Bottom 1.016: 154.3,154.14 R70.S C14.1 CX4.2 C18.1 | 154.3,154.14 R72.1 | 154.3,154.14 R71.1
N$54
  Bottom 1.016: J7.2 R73.2 R74.2
N$55
  Bottom 1.016: J7.1 R76.2 R75.2
N$56
  Bottom 1.016: J8.2 R78.2 R77.2
N$57
  Bottom 1.016: J8.1 R79.2 R80.2
N$58
  Top 1.422: B1.- 93.34,138.9 C7.- 93.34,117.31 | R82.1 93.34,117.31 | 93.34,117.31 R81.1
N$59
  Top 0.254: CX1.1 69.21,108.42 69.03,108.28
  Top 1.016: R18.1 42.54,22.06 36.19,15.71 C9.2 | CX1.1 69.03,108.28
  Top 1.27: R58.1 139.06,22.06 144.14,20.79 C10.2 | J2.1 78.1,51.27 76.83,53.81 R9.2 55.24,74.13 R17.1
  Top 1.422: B1.+ 83.18,143.98 83.18,128.74 C7.+ | 76.83,77.94 85.72,77.94 C8.+ | 76.83,77.94 R9.2 | 69.03,108.28 76.83,98.26 76.83,77.94
  Top 1.676: C8.+ 86.99,89.37 89.53,96.99 J17.1A
  Bottom 0.254: 144.14,15.71 C10.2 | 64.13,109.69 C15.2 | 71.75,154.14 C12.2 | 117.47,110.96 C17.2 | 117.46,113.3 116.2,113.5
  Bottom 1.016: R69.A 117.46,113.3 112.39,113.5 | R70.A 113.66,156.68 CX4.1 C18.2 | 67.94,110.96 67.94,112.23 64.13,112.23 | 64.13,112.23 R29.A | 64.13,156.68 67.94,156.68 67.94,154.14 | 64.13,156.68 R33.A | 71.75,154.14 67.94,154.14 | 67.94,154.14 CX3.1 | R50.2 102.23,77.94 85.72,77.94 | CX1.1 C11.2 | 64.13,112.23 64.13,109.69 | 64.13,156.68 C16.2 | CX2.1 C13.2 | 116.2,113.5 117.47,110.96 | U$3.IN R19.1 R18.1 U$4.IN | R57.1 R58.1 U$2.IN | R60.1 U$1.IN
  Bottom 1.27: CX1.1 67.94,110.96 75.56,122.39 | R26.1 R25.1 J3.1 R12.1 R11.1 85.72,8.09 89.53,13.17 | 89.53,13.17 93.34,8.09 R52.1 R51.1 J5.1 R65.1 R66.1 132.71,15.71 144.14,15.71 | R59.1 R57.1 R58.1 R60.1 | R17.1 R20.1 R19.1 | 98.42,48.73 J6.1 R53.1 R54.1 89.53,44.92 | J2.1 R13.1 R14.1 89.53,44.92 | 89.53,44.92 89.53,13.17
  Bottom 1.422: 84.45,149.06 80.64,154.14 71.75,154.14 | 84.45,149.06 B1.+ | C7.+ 84.45,127.47 75.56,122.39 104.77,122.39 | CX4.1 C14.2 104.77,154.14 104.77,149.06 | 104.77,149.06 104.77,122.39 | 104.77,122.39 112.39,113.5 CX2.1 | 104.77,149.06 84.45,149.06
  Bottom 1.676: R19.1 R18.1 | C8.+ 85.72,77.94
N$60
  Top 0.254: J13.1A 27.3,4.28 | V2.5 22.22,25.87
  Top 1.422: V1.4 48.89,20.79 48.89,25.87 V1.5 | 27.3,4.28 29.84,4.28 29.84,25.87 V2.5 | 22.22,25.87 22.22,30.95 V2.4
  Bottom 1.422: V2.5 V1.5
N$61
  Bottom 0.254: 24.76,9.36 J14.1A | 62.86,30.95 V1.9
  Bottom 1.422: 9.52,9.36 24.76,9.36 | 9.52,9.36 V2.9 | 62.86,30.95 67.94,29.68 67.94,18.25 55.24,9.36 9.52,9.36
